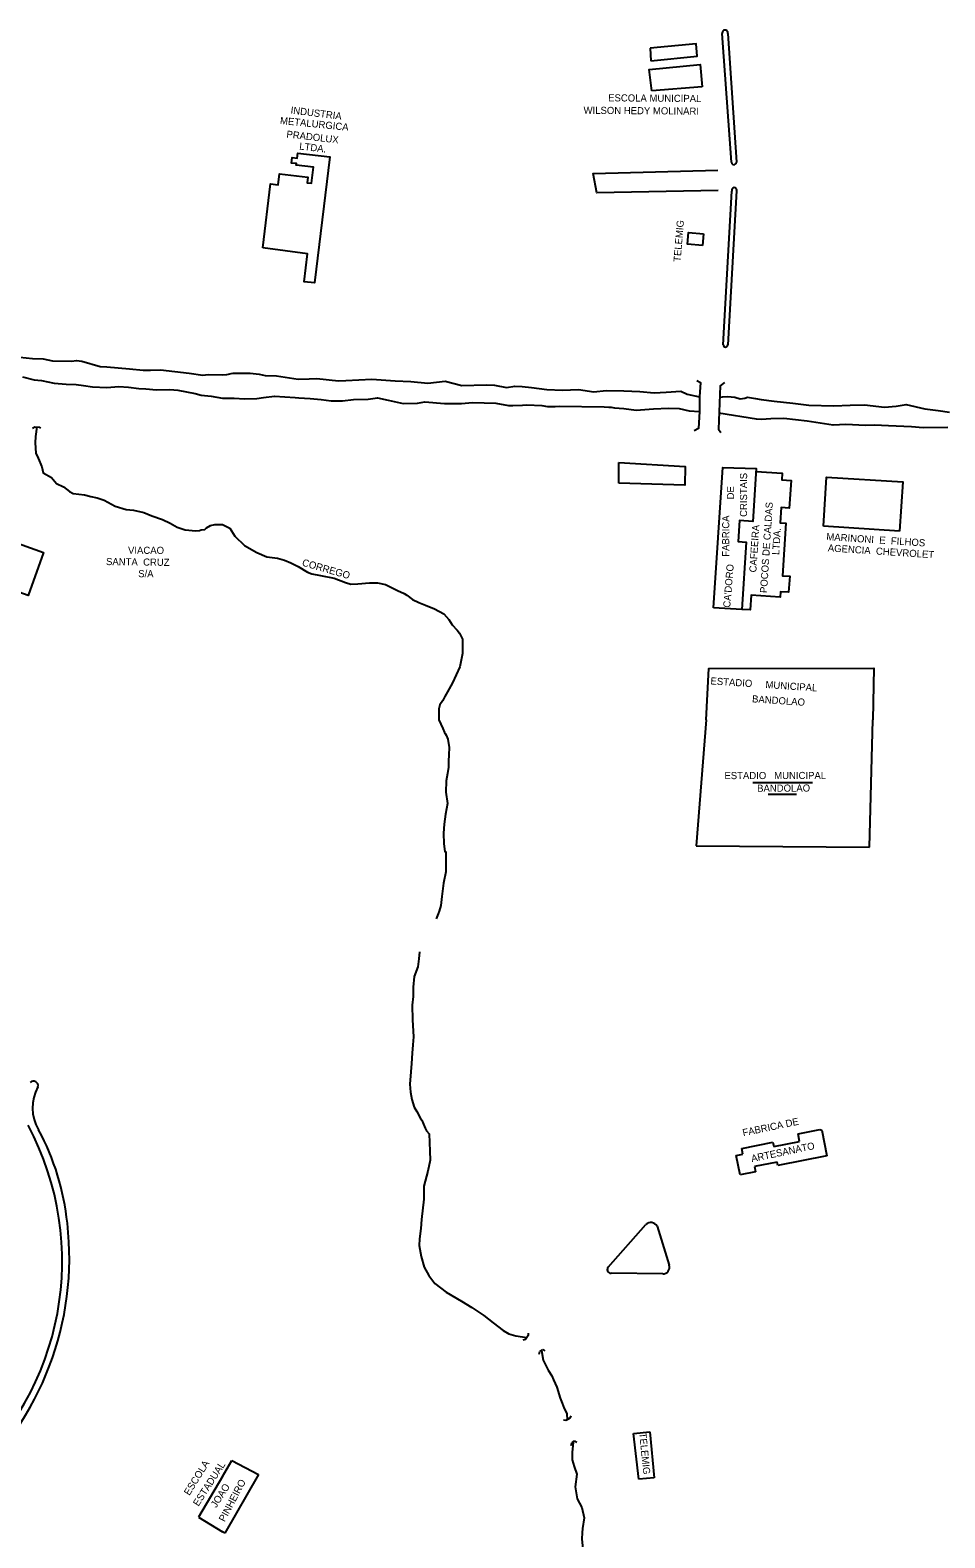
# Model space of a CAD drawing. Extents: x 325899 to 363134, y 7578590 to 7592502.
# Drawn here: x 335173 to 335687, y 7589543 to 7590389 of the extents above; entities that cross this region are included whole.
import ezdxf

# ---------------------------------------------------------------- set-up
doc = ezdxf.new("R2010")
doc.units = 0
for name, color, linetype in [('EDIFEXISTENT', 7, 'Continuous'), ('EDIFIDENTIF', 7, 'Continuous'), ('EDIFOBRAEXIS', 7, 'Continuous')]:
    doc.layers.add(name, color=color, linetype=linetype)

msp = doc.modelspace()

# ---------------------------------------------------------------- linework, layer by layer
at = {"layer": 'EDIFEXISTENT'}
for p, q in [((335552.97, 7590001.93), (335547.33, 7589931.21)), ((335644.65, 7589930.45), (335646.56, 7590001.93)), ((335547.33, 7589931.21), (335644.65, 7589930.45)), ((335604.52, 7589769.72), (335616.77, 7589772.17)), ((335605.38, 7589765.42), (335604.52, 7589769.72)), ((335616.77, 7589772.17), (335617.8, 7589771.76)), ((335617.8, 7589771.76), (335620.67, 7589757.39)), ((335569.76, 7589757.59), (335573.52, 7589758.34)), ((335572.9, 7589761.42), (335590.45, 7589764.92)), ((335573.52, 7589758.34), (335572.9, 7589761.42)), ((335590.45, 7589764.92), (335590.93, 7589762.53)), ((335590.93, 7589762.53), (335605.38, 7589765.42)), ((335571.95, 7589746.61), (335569.76, 7589757.59)), ((335592.76, 7589753.84), (335580.08, 7589751.31)), ((335580.08, 7589751.31), (335580.67, 7589748.35)), ((335593.15, 7589751.89), (335592.76, 7589753.84)), ((335620.67, 7589757.39), (335593.15, 7589751.89)), ((335580.67, 7589748.35), (335571.95, 7589746.61)), ((335452.99, 7589656.48), (335451.5, 7589654.18)), ((335452.95, 7589657.85), (335452.99, 7589656.48)), ((335451.5, 7589654.18), (335450.11, 7589653.86)), ((335459.58, 7589647.48), (335461.2, 7589648.67)), ((335461.2, 7589648.67), (335462.36, 7589647.89)), ((335459.21, 7589646.13), (335459.58, 7589647.48)), ((335474.17, 7589608.78), (335472.78, 7589609.1)), ((335476.5, 7589610.22), (335474.17, 7589608.78)), ((335477.06, 7589611.47), (335476.5, 7589610.22)), ((335477.5, 7589596.22), (335479.12, 7589597.4)), ((335479.12, 7589597.4), (335480.28, 7589596.62)), ((335512.17, 7589601.46), (335521.23, 7589602.38)), ((335515.18, 7589575.86), (335512.17, 7589601.46)), ((335521.23, 7589602.38), (335523.84, 7589576.74)), ((335477.12, 7589594.86), (335477.5, 7589596.22)), ((335281.39, 7589577.46), (335286.64, 7589586.39)), ((335286.64, 7589586.39), (335301.69, 7589578.56)), ((335281.39, 7589577.46), (335267.95, 7589554.55)), ((335301.69, 7589578.56), (335282.83, 7589545.56)), ((335523.84, 7589576.74), (335515.18, 7589575.86)), ((335267.95, 7589554.55), (335281.39, 7589546.39)), ((335282.83, 7589545.56), (335281.39, 7589546.39))]:
    msp.add_line(p, q, dxfattribs=at)
for points in [[(335521.81, 7590371.66), (335547.95, 7590374.22), (335547.25, 7590381.26), (335521.42, 7590378.71)], [(335521.42, 7590378.71), (335521.81, 7590371.66)], [(335522.47, 7590354.81), (335521.01, 7590366.71), (335549.52, 7590369.53), (335550.75, 7590357.11)], [(335550.75, 7590357.11), (335522.47, 7590354.81)], [(335304.04, 7590266.8), (335308.33, 7590302.6), (335312.73, 7590302.07), (335313.48, 7590308.29), (335329.34, 7590306.39), (335328.97, 7590303.23), (335331.5, 7590302.93), (335332.58, 7590311.97), (335322.82, 7590313.14), (335322.92, 7590314), (335320.27, 7590314.32), (335320.65, 7590317.46), (335323.39, 7590317.13), (335323.72, 7590319.89), (335341.62, 7590317.74), (335333.14, 7590247.03), (335327.39, 7590247.72), (335329.26, 7590263.33), (335304.04, 7590266.8)], [(335550.89, 7590268.12), (335542.52, 7590268.82), (335543.07, 7590275.4), (335551.43, 7590274.65)], [(335551.43, 7590274.65), (335550.89, 7590268.12)], [(335547.65, 7590192.32), (335549.8, 7590191.22), (335549.23, 7590183.07), (335549.14, 7590174.97), (335548.61, 7590165.32), (335546.25, 7590164.14)], [(335563.21, 7590191.11), (335560.71, 7590189.39), (335559.79, 7590164.94), (335561.18, 7590163.13)], [(335174.87, 7590165.65), (335176.08, 7590166.4), (335178.52, 7590166.21), (335179.29, 7590165.51)], [(335503.93, 7590146.3), (335541.23, 7590144.06), (335541.04, 7590133.55), (335503.99, 7590134.65)], [(335503.99, 7590134.65), (335503.93, 7590146.3)], [(335557.04, 7590064.85), (335562.28, 7590143.52), (335581.1, 7590142.87), (335579.17, 7590113.24), (335571.62, 7590113.73), (335570.85, 7590101.91), (335575.42, 7590101.61), (335572.96, 7590063.75), (335557.04, 7590064.85)], [(335580.99, 7590141.21), (335595.6, 7590140.26), (335595.36, 7590136.54), (335600.56, 7590136.2), (335599.55, 7590120.7), (335594.96, 7590121), (335594.41, 7590112.48), (335597.74, 7590112.26), (335595.82, 7590082.74), (335599.82, 7590082.48), (335599.23, 7590073.5), (335594.7, 7590073.79), (335594.51, 7590070.82), (335578.13, 7590071.88), (335577.59, 7590063.61), (335572.96, 7590063.75)], [(335618.74, 7590110.64), (335620.53, 7590138.15), (335663.3, 7590135.36), (335661.5, 7590107.69)], [(335115.75, 7590119.18), (335181.05, 7590095.82), (335172.38, 7590071.59), (335161.85, 7590075.36), (335150.99, 7590045.02), (335130.47, 7590052.36), (335129.71, 7590050.24), (335123.3, 7590052.54), (335124.08, 7590054.72), (335112.44, 7590058.89), (335118.31, 7590075.28), (335113.43, 7590077.03), (335118.95, 7590092.45), (335107.98, 7590096.37)], [(335661.5, 7590107.69), (335618.74, 7590110.64)], [(335552.97, 7590001.93), (335554.51, 7590030.77), (335647.1, 7590030.94), (335646.56, 7590001.93)]]:
    msp.add_lwpolyline(points, dxfattribs=at)
at = {"layer": 'EDIFOBRAEXIS'}
for points in [[(335567.21, 7590314.78), (335561.91, 7590386.96)], [(335565.18, 7590386.95), (335569.93, 7590314.79)], [(335559.75, 7590298.9), (335491.6, 7590297.62), (335489.45, 7590308.51), (335559.42, 7590310.25)], [(335562.57, 7590212.32), (335567.4, 7590298.6)], [(335570.06, 7590298.64), (335565.04, 7590212.23)], [(335127.24, 7590208.26), (335144.39, 7590206.53), (335150.16, 7590206.82), (335159.36, 7590206.58), (335167.65, 7590205.44), (335174.8, 7590204.62), (335180.88, 7590204.46), (335185.95, 7590203.35), (335196.77, 7590203.09), (335199.54, 7590203.47), (335202.54, 7590203.18), (335212.7, 7590200.21), (335216.52, 7590199.9), (335229.19, 7590198.82), (335236.87, 7590198.04), (335241.05, 7590198.06), (335246.57, 7590198.38), (335262.75, 7590196.5), (335270.48, 7590195.36), (335273.49, 7590195.64), (335281.39, 7590195.43)], [(335169.14, 7590194.38), (335175.79, 7590192.67), (335179.89, 7590192.27), (335186.89, 7590190.82), (335193.71, 7590190.21), (335199.26, 7590190.14), (335203.52, 7590189.56), (335208.55, 7590188.74), (335216.5, 7590188.4), (335223.28, 7590188.9), (335228.65, 7590188.48), (335234.48, 7590187.76), (335238.44, 7590187.61), (335244.44, 7590187.09), (335251.89, 7590187.24), (335256.32, 7590186.88), (335266.05, 7590185.03), (335269.44, 7590184.01), (335275.06, 7590183.45), (335281.39, 7590182.43)], [(335281.39, 7590195.43), (335283.93, 7590195.68), (335284.81, 7590195.79), (335286.31, 7590196.22), (335287.41, 7590196.47), (335295.28, 7590196.41), (335296.93, 7590196.37), (335302.08, 7590195.77), (335305.36, 7590195.17), (335311.81, 7590194.99), (335323.96, 7590192.98), (335330.16, 7590193.2), (335334.43, 7590193.46), (335346.64, 7590192.06), (335350.76, 7590192.24), (335365.34, 7590193.04), (335378.44, 7590192.19), (335387.18, 7590191.72), (335396.65, 7590190.81), (335406.53, 7590191.88), (335415.71, 7590189.53), (335429.53, 7590189.8), (335434.08, 7590189.62), (335440.85, 7590188.4), (335445.56, 7590189.16), (335449.59, 7590188.86), (335454.95, 7590188.38), (335463.45, 7590187.28), (335472.29, 7590186.93), (335481.21, 7590187.32), (335489.86, 7590185.91), (335496.82, 7590186.67), (335506.8, 7590186.52), (335515.72, 7590186.22), (335523.82, 7590185.32), (335530.42, 7590185.85), (335538.65, 7590186.27), (335542.2, 7590184.68), (335549.23, 7590183.07)], [(335281.39, 7590182.43), (335283.35, 7590182.42), (335283.68, 7590182.47), (335284.96, 7590182.38), (335287.98, 7590182.42), (335293.82, 7590181.97), (335300.65, 7590182.29), (335304.51, 7590182.68), (335310.64, 7590183.59), (335322.19, 7590182.82), (335324.3, 7590182.54), (335330.59, 7590182.2), (335336.79, 7590181.66), (335342.4, 7590180.95), (335348.9, 7590180.87), (335355.08, 7590181.63), (335363.13, 7590181.75), (335368.49, 7590182.51), (335374.4, 7590181.21), (335382.95, 7590179.37), (335390.93, 7590179.54), (335395.1, 7590180.3), (335405.99, 7590179.44), (335415.67, 7590179.32), (335421.79, 7590180.03), (335434.87, 7590179.61), (335442.05, 7590178.28), (335444.49, 7590178.35), (335449.9, 7590178.53), (335452.21, 7590178.72), (335460.77, 7590178.2), (335463.94, 7590177.67), (335468.11, 7590177.71), (335470.39, 7590177.9), (335495.77, 7590177.45), (335498.3, 7590177.36), (335499.68, 7590177.25), (335501.48, 7590177.02), (335506.73, 7590176.61), (335513.74, 7590175.74), (335523.47, 7590176.41), (335531.75, 7590176.83), (335537.87, 7590176.55), (335543.35, 7590175.35), (335549.14, 7590174.97)], [(335560.47, 7590182.88), (335562.11, 7590183.14), (335564.93, 7590183.25), (335569.07, 7590182.88), (335572.01, 7590182.03), (335574.68, 7590182.37), (335576.2, 7590182.92), (335580.67, 7590182.14), (335583.77, 7590181.67), (335591.13, 7590180.62), (335601.56, 7590179.53), (335610.55, 7590178.52), (335624.59, 7590178.15), (335633.76, 7590178.49), (335641.79, 7590178.58), (335653.08, 7590177.31), (335659.51, 7590177.91), (335665.26, 7590178.78), (335675.66, 7590176.39), (335683.15, 7590175.49), (335689.54, 7590174.57)], [(335688.64, 7590165.94), (335674.8, 7590165.73), (335668.2, 7590166.39), (335655.32, 7590166.83), (335647.45, 7590167.25), (335642.44, 7590166.99), (335631.32, 7590167.71), (335624.18, 7590167.18), (335609.62, 7590169.41), (335596.54, 7590170.99), (335589.15, 7590170.8), (335583.94, 7590170.44), (335581.23, 7590170.66), (335560.13, 7590173.93)], [(335177.2, 7590166.31), (335176.55, 7590160.86), (335176.4, 7590157.31), (335176.59, 7590151.56), (335178.03, 7590148.7), (335180.04, 7590143.96), (335180.78, 7590140.46), (335185.4, 7590137.83), (335188.29, 7590134.44), (335192.24, 7590132.61), (335195.49, 7590129.94), (335197.65, 7590128.86), (335203.98, 7590128.22), (335207.6, 7590127.17), (335211.16, 7590126.49), (335215.03, 7590125.11), (335221.28, 7590121.78), (335227.31, 7590119.89), (335231.56, 7590119.56), (335237.31, 7590118.2), (335241.72, 7590116.32), (335247.81, 7590114.33), (335252.11, 7590112.33), (335256.02, 7590110.01), (335260.52, 7590108.44), (335266.52, 7590107.9), (335268.61, 7590108.12), (335269.49, 7590108.5), (335271.45, 7590108.72), (335272.46, 7590109.67), (335274.71, 7590111.03), (335277.2, 7590111.55), (335281.39, 7590111.45)], [(335281.39, 7590111.45), (335285.61, 7590109.51), (335288.43, 7590104.96), (335293.73, 7590099.74), (335300.68, 7590095.72), (335306.35, 7590093.35), (335312.36, 7590092.62), (335316.17, 7590091.49), (335319.73, 7590089.99), (335323.9, 7590087.87), (335329.26, 7590084.84), (335331.62, 7590083.75), (335336.38, 7590082.96), (335344.06, 7590081.45), (335350.45, 7590078.91), (335353.53, 7590078.06), (335357.46, 7590078.24), (335363.92, 7590078.87), (335368.52, 7590078.86), (335372.87, 7590077.82), (335379.76, 7590074.51), (335383.5, 7590072.78), (335384.9, 7590071.81), (335388.05, 7590069.52), (335391.66, 7590067.67), (335395.34, 7590066.21), (335400.38, 7590064.12), (335405.72, 7590061.44), (335408.56, 7590058.26), (335410.39, 7590055.23), (335413.09, 7590052.15), (335414.46, 7590050.47), (335416.18, 7590047.27), (335416.15, 7590039.05), (335414.67, 7590031.65), (335410.47, 7590022.71), (335407.77, 7590017.7), (335406.27, 7590015.03), (335405.12, 7590012.74), (335403.52, 7590010.35), (335402.87, 7590008.14), (335402.84, 7590001.91)], [(335402.84, 7590001.91), (335405.07, 7589997.11), (335406.15, 7589994.77), (335406.45, 7589994.19), (335406.95, 7589993.29), (335407.85, 7589991.11), (335408.73, 7589986.45), (335408.59, 7589982.33), (335408.38, 7589978.8), (335408.29, 7589975.31), (335407.67, 7589971.86), (335407.04, 7589967.63), (335406.9, 7589961.4), (335407.73, 7589955.07), (335406.67, 7589948.97), (335405.8, 7589943.38), (335405.5, 7589938.32), (335405.61, 7589932.35), (335406.21, 7589927.97), (335406.75, 7589927.8), (335406.81, 7589916.6), (335405.55, 7589910.26), (335404.48, 7589902.74), (335404, 7589897.69), (335403.04, 7589894.62), (335402.42, 7589893.13), (335401.48, 7589890.28)], [(335579.21, 7589966.75), (335612.66, 7589966.75)], [(335587.72, 7589960.23), (335603.56, 7589960.23)], [(335392.08, 7589871.84), (335391.7, 7589867.82), (335391.01, 7589863.28), (335389.04, 7589857.86), (335388.44, 7589851.93), (335388.4, 7589846.69), (335387.99, 7589841.85), (335388.05, 7589833.67), (335388.74, 7589824.08), (335388.27, 7589819.67), (335387.99, 7589814.99), (335387.61, 7589809.16), (335387.15, 7589804.35), (335386.64, 7589797.52), (335387.07, 7589792.96), (335387.73, 7589788.86), (335389.09, 7589784.53), (335390.55, 7589782.15), (335392.64, 7589778.22), (335393.35, 7589777.32), (335395.22, 7589772.87), (335396.02, 7589771.37), (335397.38, 7589769.73), (335397.85, 7589759.85), (335398.03, 7589754.95), (335396.72, 7589748.62), (335394.53, 7589740.25), (335394.51, 7589733.03), (335393.19, 7589721.61), (335392.84, 7589716.5), (335391.97, 7589710.83), (335391.82, 7589706.94), (335392.89, 7589700.9), (335394.6, 7589694.89), (335397.34, 7589690.19), (335400.66, 7589685.65), (335406.94, 7589680.86), (335415.65, 7589675.73), (335421.48, 7589672.27), (335428.2, 7589667.8), (335433.36, 7589663.59), (335439.07, 7589659.28), (335442.14, 7589657.44), (335446.2, 7589656.26), (335452.34, 7589655.41)], [(335497.88, 7589694.83), (335519.1, 7589718.72)], [(335525.44, 7589717.78), (335532.11, 7589695.93)], [(335528.53, 7589691.12), (335499.56, 7589691.43)], [(335460.48, 7589648.14), (335461.51, 7589642.68), (335464.3, 7589637.01), (335466.26, 7589633.94), (335467.29, 7589631.6), (335469.07, 7589627.58), (335471.08, 7589621.35), (335472.04, 7589618.46), (335473.16, 7589615.51), (335474.02, 7589614.24), (335474.8, 7589612.63), (335475, 7589609.16)], [(335478.27, 7589596.74), (335477.77, 7589590.79), (335477.75, 7589589.49), (335477.77, 7589586.8), (335478.94, 7589582.96), (335480.34, 7589578.71), (335479.41, 7589571.67), (335480.61, 7589564.92), (335483.23, 7589559.93), (335484.44, 7589554.22), (335483.44, 7589548.17), (335483.37, 7589545.75), (335483.2, 7589542.47), (335483.79, 7589536.69), (335484.43, 7589533.48), (335485.5, 7589523.75), (335485.22, 7589517.82), (335485.76, 7589512.12)]]:
    msp.add_lwpolyline(points, dxfattribs=at)
for centre, radius, start, end in [((335563.55, 7590387.2), 1.66, 351.11003, 188.36052), ((335568.57, 7590314.75), 1.36, 178.67427, 1.86719), ((335568.72, 7590299.09), 1.41, 341.27641, 200.62459), ((335563.81, 7590212.32), 1.23, 180.11797, 355.80964), ((335175.33, 7589796.67), 2.58, 344.30152, 135.48853), ((335199.13, 7589784.32), 24.3, 151.342, 210.55336), ((335030.16, 7589698.24), 161.3, 310.7673, 28.21736), ((335054.28, 7589705.05), 140.84, 5.88716, 28.36832), ((335025.25, 7589700.02), 170.25, 311.54311, 6.56883), ((335521.92, 7589715.86), 4.01, 28.51983, 134.64742), ((335499.66, 7589693.52), 2.21, 143.56438, 199.73623), ((335499.5, 7589693.47), 2.04, 199.93676, 271.77177), ((335528.72, 7589694.72), 3.6, 266.94894, 19.70384)]:
    msp.add_arc(centre, radius, start, end, dxfattribs=at)

# ---------------------------------------------------------------- texts
at = {"layer": 'EDIFIDENTIF'}
for s, rotation, p in [('ESCOLA MUNICIPAL', 359.54642, (335497.92, 7590348.92)), ('INDUSTRIA', 352.93957, (335319.52, 7590342.1)), ('WILSON HEDY MOLINARI', 359.54642, (335484.12, 7590341.94)), ('METALURGICA', 354.25248, (335313.6, 7590336.26)), ('PRADOLUX', 353.61766, (335317.19, 7590328.6)), ('LTDA.', 353.11162, (335324.39, 7590321.93)), ('TELEMIG ', 85.26662, (335538.56, 7590258.75)), ('CRISTAIS', 89.8266, (335575.88, 7590115.78)), ('DE', 89.8266, (335568.62, 7590125.57)), ('POCOS DE CALDAS', 86.27757, (335587.08, 7590072.96)), ('FABRICA', 89.8266, (335565.87, 7590093.42)), ('CAFEEIRA', 86.27757, (335581.09, 7590084.53)), ('LTDA.', 86.27757, (335593.91, 7590094.36)), ('MARINONI  E  FILHOS', 356.27757, (335620.31, 7590102.78)), ('VIACAO', 359.77225, (335228.42, 7590095.09)), ('AGENCIA  CHEVROLET', 356.27757, (335621.14, 7590096.43)), ('SANTA  CRUZ  ', 359.22282, (335216.06, 7590088.75)), ('CORREGO', 343.94888, (335325.81, 7590088.49)), ("CA'DORO", 85.19622, (335566.42, 7590064.71)), ('S/A', 359.37479, (335234.12, 7590081.97)), ('ESTADIO     MUNICIPAL', 356.18888, (335555.27, 7590021.83)), ('BANDOLAO', 356.18888, (335578.61, 7590011.75)), ('ESTADIO   MUNICIPAL', 0.09153, (335563.2, 7589968.65)), ('BANDOLAO', 0.22931, (335581.56, 7589961.56)), ('FABRICA DE', 11.78258, (335573.79, 7589768.26)), ('ARTESANATO', 11.78258, (335578.63, 7589753.76)), ('TELEMIG', 275.71124, (335515.36, 7589601.78)), ('ESCOLA', 58.30724, (335262.88, 7589566.43)), ('ESTADUAL', 57.17597, (335267.94, 7589560.37)), ('JOAO', 57.17597, (335277.92, 7589559.56)), ('PINHEIRO', 62.18259, (335282.65, 7589551.64))]:
    msp.add_text(s, height=4, rotation=rotation, dxfattribs=at).set_placement(p)

doc.saveas('drawing.dxf')
